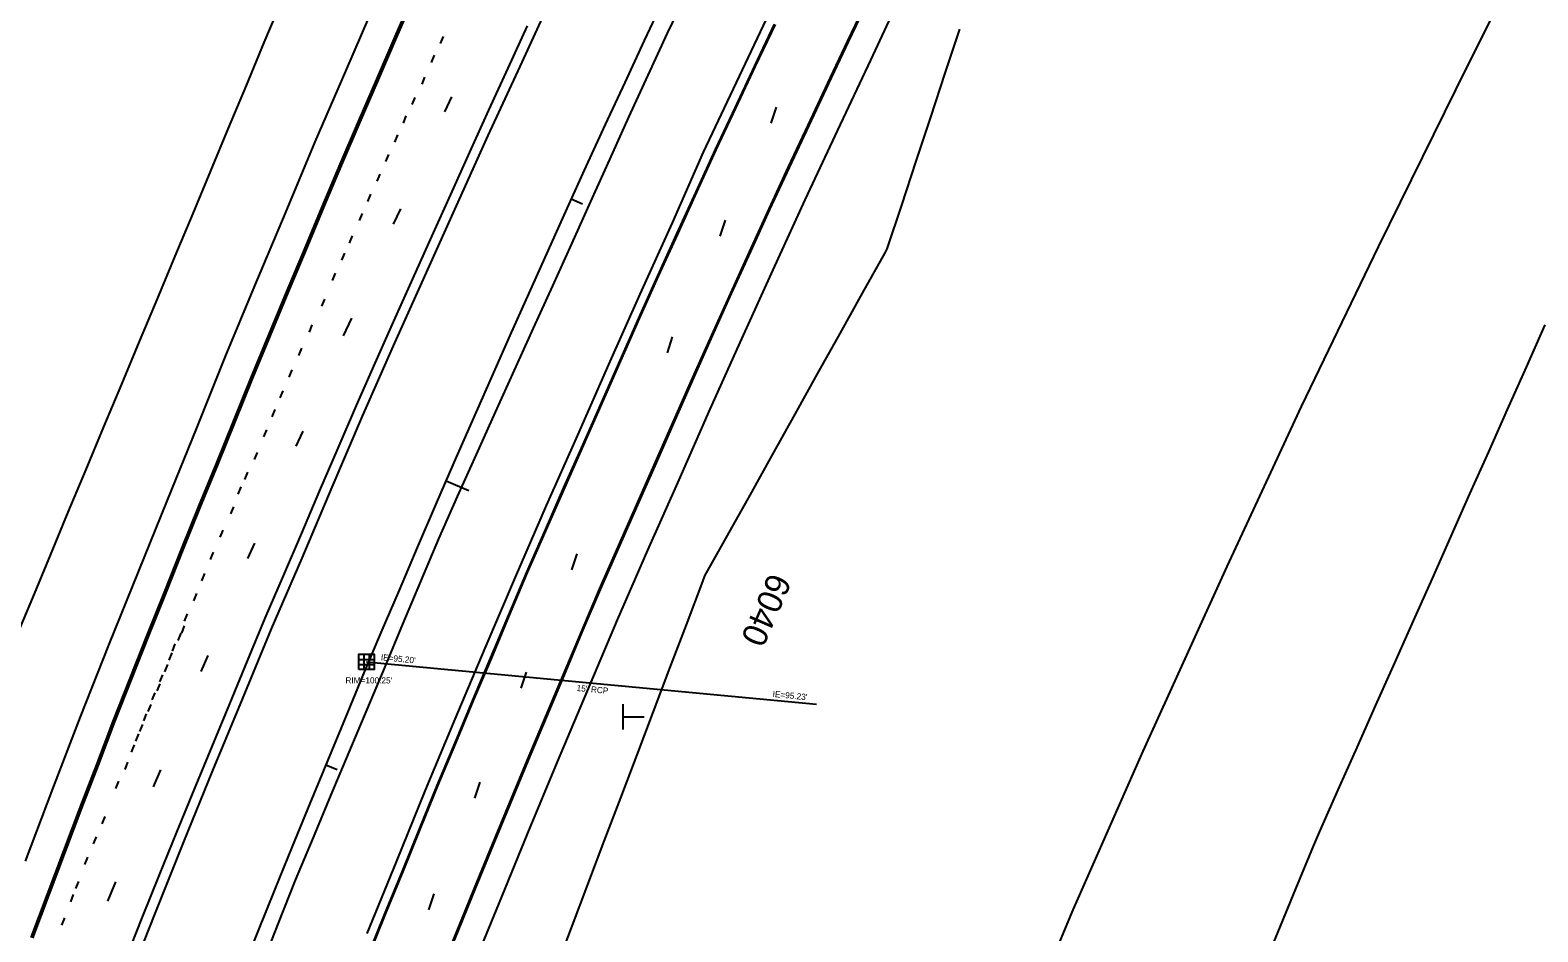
# Model space of a CAD drawing. Extents: x 2132221 to 2141942, y 535736 to 547298.
# Drawn here: x 2136377.6 to 2136866.6, y 537794.1 to 538086.4 of the extents above; entities that cross this region are included whole.
import ezdxf

# ---------------------------------------------------------------- set-up
doc = ezdxf.new("R2010")
doc.units = 0
for name, color, linetype in [('RD_EX_BldgApp', 7, 'Continuous'), ('RD_EX_Conc', 7, 'Continuous'), ('RD_EX_DR_Inlet', 7, 'Continuous'), ('RD_EX_DR_Inlet_txCode', 7, 'Continuous'), ('RD_EX_DR_Pipe', 7, 'Continuous'), ('RD_EX_DR_Pipe_txCode', 7, 'Continuous'), ('RD_EX_Fence_Other', 7, 'Continuous'), ('RD_EX_GuardRail', 7, 'Continuous'), ('RD_EX_Misc', 7, 'Continuous'), ('RD_EX_Road', 7, 'Continuous'), ('RD_EX_VEG', 7, 'Continuous'), ('RD_HC_Cl', 7, 'Continuous'), ('RD_HC_Data_Tic', 7, 'Continuous'), ('RD_HC_TX_Sta50', 7, 'Continuous'), ('TOPO_E_TLIML-Line', 7, 'Continuous')]:
    doc.layers.add(name, color=color, linetype=linetype)

msp = doc.modelspace()

# ---------------------------------------------------------------- linework, layer by layer
at = {"layer": 'RD_EX_BldgApp'}
for p, q in [((2136569.86, 537867.87), (2136569.86, 537863.75)), ((2136569.86, 537863.75), (2136569.86, 537859.64)), ((2136569.86, 537863.75), (2136576.72, 537863.75))]:
    msp.add_line(p, q, dxfattribs=at)
at = {"layer": 'RD_EX_Conc'}
for points in [[(2136377.94, 537792.23), (2136383.21, 537806.27), (2136388.51, 537820.3), (2136393.84, 537834.33), (2136399.18, 537848.34), (2136404.54, 537862.35), (2136409.99, 537876.34), (2136415.51, 537890.29), (2136421.11, 537904.2), (2136426.72, 537918.11), (2136432.35, 537932.02), (2136438, 537945.92), (2136443.63, 537959.82), (2136449.25, 537973.73), (2136454.98, 537987.59), (2136460.75, 538001.44), (2136466.53, 538015.28), (2136472.33, 538029.12), (2136478.15, 538042.95), (2136484.07, 538056.73), (2136490.02, 538070.5), (2136495.93, 538084.29), (2136501.94, 538098.03)], [(2136510.69, 537780.38), (2136516.36, 537794.27), (2136522.05, 537808.15), (2136527.73, 537822.03), (2136533.45, 537835.89), (2136539.22, 537849.74), (2136545.05, 537863.56), (2136550.89, 537877.38), (2136556.68, 537891.21), (2136562.58, 537905), (2136568.59, 537918.74), (2136574.67, 537932.45), (2136580.76, 537946.16), (2136586.79, 537959.9), (2136592.85, 537973.62), (2136598.94, 537987.32), (2136605.12, 538000.99), (2136611.32, 538014.65), (2136617.55, 538028.29), (2136623.86, 538041.9), (2136630.26, 538055.46), (2136636.63, 538069.04), (2136643.01, 538082.62), (2136649.46, 538096.16)], [(2136487.01, 537785.95), (2136492.62, 537799.86), (2136498.33, 537813.74), (2136503.97, 537827.63), (2136509.63, 537841.53), (2136515.4, 537855.37), (2136521.21, 537869.2), (2136527.05, 537883.02), (2136532.85, 537896.85), (2136538.69, 537910.67), (2136544.69, 537924.42), (2136550.74, 537938.15), (2136556.84, 537951.85), (2136562.88, 537965.58), (2136568.91, 537979.31), (2136575.01, 537993.02), (2136581.17, 538006.7), (2136587.39, 538020.35), (2136593.6, 538034), (2136599.84, 538047.65), (2136606.24, 538061.21), (2136612.65, 538074.77), (2136619.07, 538088.33)]]:
    msp.add_lwpolyline(points, dxfattribs=at)
at = {"layer": 'RD_EX_DR_Inlet'}
for p, q in [((2136484.16, 537882.41), (2136489.16, 537882.41)), ((2136485.86, 537884.11), (2136485.86, 537879.11)), ((2136487.56, 537884.11), (2136487.56, 537879.11)), ((2136484.16, 537880.71), (2136489.16, 537880.71))]:
    msp.add_line(p, q, dxfattribs=at)
msp.add_lwpolyline([(2136484.16, 537879.11), (2136484.16, 537884.11), (2136489.16, 537884.11), (2136489.16, 537879.11)], close=True, dxfattribs=at)
at = {"layer": 'RD_EX_DR_Pipe'}
msp.add_line((2136486.69, 537881.56), (2136632.62, 537867.86), dxfattribs=at)
at = {"layer": 'RD_EX_Fence_Other'}
msp.add_lwpolyline([(2136917.56, 538219.98), (2136890.82, 538168.74), (2136867.21, 538121.82), (2136843.5, 538074.27), (2136814.83, 538016.13), (2136789.9, 537964.36), (2136765.69, 537912.51), (2136738.54, 537852.61), (2136715.83, 537801.24), (2136694.15, 537749.42), (2136674.71, 537701.68), (2136655.13, 537652.11), (2136635.21, 537599.51), (2136616.78, 537549.09), (2136595.01, 537486.59), (2136577.24, 537436.55), (2136562.65, 537393.15), (2136547.82, 537347.2), (2136530.56, 537291.65)], dxfattribs=at)
at = {"layer": 'RD_EX_GuardRail'}
msp.add_lwpolyline([(2136452.64, 537782.88), (2136458.16, 537796.83), (2136463.67, 537810.78), (2136469.44, 537824.62), (2136475.25, 537838.45), (2136481.06, 537852.28), (2136486.88, 537866.11), (2136492.69, 537879.94), (2136498.5, 537893.76), (2136504.31, 537907.59), (2136510.12, 537921.42), (2136516.15, 537935.16), (2136522.33, 537948.82), (2136528.52, 537962.49), (2136534.7, 537976.15), (2136540.89, 537989.82), (2136547.07, 538003.48), (2136553.26, 538017.15), (2136559.44, 538030.82), (2136565.63, 538044.48), (2136571.81, 538058.15), (2136577.99, 538071.81), (2136584.35, 538085.4), (2136590.8, 538098.94)], dxfattribs=at)
at = {"layer": 'RD_EX_Misc'}
for p, q in [((2136510.7, 538082.02), (2136511.65, 538084.37)), ((2136507.77, 538075.91), (2136508.72, 538078.26)), ((2136504.7, 538068.83), (2136505.64, 538071.17)), ((2136501.52, 538062.23), (2136502.47, 538064.57)), ((2136512.07, 538059.95), (2136514.31, 538064.8)), ((2136498.64, 538056.22), (2136499.59, 538058.56)), ((2136617.98, 538056.23), (2136619.7, 538061.42)), ((2136495.91, 538050.08), (2136496.86, 538052.42)), ((2136492.98, 538043.76), (2136493.93, 538046.11)), ((2136490.13, 538037.4), (2136491.08, 538039.74)), ((2136487.13, 538030.83), (2136488.08, 538033.18)), ((2136495.41, 538023.43), (2136497.87, 538028.49)), ((2136484.4, 538024.63), (2136485.35, 538026.97)), ((2136601.37, 538019.61), (2136603.09, 538024.8)), ((2136481.22, 538017.34), (2136482.17, 538019.69)), ((2136478.68, 538011.77), (2136479.63, 538014.12)), ((2136475.65, 538005.27), (2136476.6, 538007.62)), ((2136472.18, 537996.88), (2136473.12, 537999.22)), ((2136468.16, 537988.5), (2136469.11, 537990.84)), ((2136479.26, 537987.26), (2136481.88, 537993.01)), ((2136584.26, 537981.74), (2136585.98, 537986.93)), ((2136464.74, 537980.88), (2136465.69, 537983.23)), ((2136461.59, 537973.9), (2136462.54, 537976.24)), ((2136458.69, 537967.14), (2136459.64, 537969.48)), ((2136456.09, 537961.03), (2136457.04, 537963.38)), ((2136453.37, 537954.5), (2136454.31, 537956.84)), ((2136463.87, 537951.48), (2136466.14, 537956.42)), ((2136450.35, 537947.17), (2136451.3, 537949.51)), ((2136447.19, 537940.75), (2136448.14, 537943.1)), ((2136445.05, 537935.96), (2136446, 537938.31)), ((2136442.66, 537929.55), (2136443.61, 537931.89)), ((2136439.19, 537921.96), (2136440.14, 537924.3)), ((2136436.12, 537914.82), (2136437.07, 537917.17)), ((2136448.23, 537915.14), (2136450.47, 537920.11)), ((2136553.27, 537911.4), (2136554.98, 537916.59)), ((2136433.28, 537907.88), (2136434.23, 537910.23)), ((2136430.67, 537901.37), (2136431.62, 537903.71)), ((2136427.66, 537894.78), (2136428.61, 537897.13)), ((2136425.61, 537888.53), (2136426.56, 537890.87)), ((2136426.73, 537890.92), (2136427.68, 537893.27)), ((2136423.71, 537885.06), (2136424.65, 537887.4)), ((2136422.68, 537882.17), (2136423.63, 537884.52)), ((2136433.02, 537878.48), (2136435.29, 537883.64)), ((2136419.65, 537875.09), (2136420.6, 537877.43)), ((2136421.31, 537878.36), (2136422.26, 537880.71)), ((2136536.85, 537873.02), (2136538.56, 537878.22)), ((2136417.2, 537869.24), (2136418.15, 537871.58)), ((2136418.77, 537872.16), (2136419.72, 537874.5)), ((2136415.88, 537865.47), (2136416.83, 537867.82)), ((2136414.41, 537862.44), (2136415.36, 537864.79)), ((2136411.87, 537855.89), (2136412.82, 537858.24)), ((2136413.19, 537858.97), (2136414.14, 537861.32)), ((2136410.46, 537852.32), (2136411.41, 537854.67)), ((2136408.36, 537846.75), (2136409.31, 537849.1)), ((2136405.38, 537840.55), (2136406.33, 537842.89)), ((2136417.59, 537841.07), (2136419.93, 537846.54)), ((2136521.87, 537837.39), (2136523.59, 537842.59)), ((2136400.93, 537829.11), (2136401.88, 537831.46)), ((2136398.15, 537822.56), (2136399.1, 537824.91)), ((2136395.32, 537815.91), (2136396.27, 537818.26)), ((2136392.44, 537808.09), (2136393.39, 537810.44)), ((2136402.74, 537803.99), (2136405.34, 537810.3)), ((2136390.73, 537803.79), (2136391.68, 537806.14)), ((2136506.89, 537801.15), (2136508.61, 537806.35)), ((2136387.9, 537796.27), (2136388.84, 537798.61))]:
    msp.add_line(p, q, dxfattribs=at)
for points in [[(2136378.48, 537792.02), (2136383.76, 537806.06), (2136389.06, 537820.1), (2136394.39, 537834.12), (2136399.73, 537848.13), (2136405.09, 537862.14), (2136410.53, 537876.12), (2136416.05, 537890.07), (2136421.65, 537903.99), (2136427.26, 537917.89), (2136432.89, 537931.8), (2136438.54, 537945.7), (2136444.17, 537959.6), (2136449.79, 537973.51), (2136455.52, 537987.37), (2136461.29, 538001.22), (2136467.07, 538015.06), (2136472.86, 538028.89), (2136478.68, 538042.72), (2136484.61, 538056.5), (2136490.56, 538070.27), (2136496.47, 538084.05), (2136502.47, 538097.8)], [(2136510.39, 537780.5), (2136516.06, 537794.39), (2136521.76, 537808.27), (2136527.43, 537822.15), (2136533.16, 537836.02), (2136538.93, 537849.86), (2136544.76, 537863.68), (2136550.59, 537877.5), (2136556.39, 537891.34), (2136562.29, 537905.13), (2136568.3, 537918.87), (2136574.38, 537932.58), (2136580.47, 537946.29), (2136586.5, 537960.03), (2136592.55, 537973.75), (2136598.65, 537987.45), (2136604.83, 538001.12), (2136611.03, 538014.78), (2136617.25, 538028.43), (2136623.57, 538042.03), (2136629.97, 538055.6), (2136636.34, 538069.18), (2136642.72, 538082.75), (2136649.17, 538096.3)], [(2136408.4, 537784.67), (2136413.93, 537798.61), (2136419.53, 537812.53), (2136425.15, 537826.43), (2136430.84, 537840.31), (2136436.57, 537854.18), (2136442.32, 537868.03), (2136448.08, 537881.88), (2136453.86, 537895.72), (2136459.81, 537909.49), (2136465.7, 537923.29), (2136471.53, 537937.11), (2136477.44, 537950.89), (2136483.39, 537964.66), (2136489.45, 537978.38), (2136495.54, 537992.09), (2136501.68, 538005.78), (2136507.83, 538019.46), (2136514, 538033.13), (2136520.16, 538046.81), (2136526.37, 538060.46), (2136532.61, 538074.1), (2136538.87, 538087.73)], [(2136487.24, 537785.86), (2136492.85, 537799.77), (2136498.56, 537813.64), (2136504.2, 537827.54), (2136509.86, 537841.43), (2136515.63, 537855.28), (2136521.44, 537869.11), (2136527.28, 537882.93), (2136533.08, 537896.76), (2136538.92, 537910.57), (2136544.91, 537924.32), (2136550.96, 537938.05), (2136557.07, 537951.75), (2136563.1, 537965.48), (2136569.14, 537979.21), (2136575.23, 537992.92), (2136581.4, 538006.6), (2136587.62, 538020.24), (2136593.83, 538033.9), (2136600.06, 538047.54), (2136606.47, 538061.11), (2136612.88, 538074.67), (2136619.3, 538088.22)]]:
    msp.add_lwpolyline(points, dxfattribs=at)
at = {"layer": 'RD_EX_Road'}
for points in [[(2136376.1, 537817), (2136384.98, 537840.38), (2136393.92, 537863.73), (2136403.07, 537887), (2136412.75, 537910.81), (2136422.11, 537934), (2136431.53, 537957.16), (2136440.87, 537980.36), (2136450.48, 538003.44), (2136460.37, 538027.1), (2136470.05, 538050.16), (2136479.98, 538073.11), (2136490.13, 538096.78)], [(2136408.91, 537776.83), (2136418.1, 537800.06), (2136427.45, 537823.25), (2136436.86, 537846.41), (2136446.43, 537869.51), (2136455.91, 537892.26), (2136465.82, 537915.21), (2136475.51, 537938.26), (2136485.39, 537961.22), (2136495.49, 537984.09), (2136505.59, 538006.63), (2136515.88, 538029.42), (2136526.19, 538052.19), (2136536.47, 538074.61), (2136546.91, 538097.32)], [(2136520.13, 537779.95), (2136529.61, 537803.04), (2136539.02, 537826.07), (2136548.62, 537849.15), (2136558.39, 537872.17), (2136568.06, 537895.22), (2136577.93, 537917.81), (2136588.1, 537940.65), (2136598.17, 537963.53), (2136608.41, 537986.34), (2136618.56, 538008.71), (2136628.92, 538031.39), (2136639.58, 538054), (2136650.24, 538076.62), (2136660.7, 538099.01)], [(2136486.88, 537793.58), (2136496.4, 537816.73), (2136505.81, 537840), (2136515.47, 537863.05), (2136525.22, 537886.07), (2136534.99, 537909.09), (2136545.09, 537932.25), (2136555.26, 537955.09), (2136565.3, 537977.98), (2136575.46, 538000.83), (2136585.95, 538023.88), (2136595.99, 538046.84), (2136606.67, 538069.44), (2136617.39, 538092.03)]]:
    msp.add_lwpolyline(points, dxfattribs=at)
at = {"layer": 'RD_EX_VEG'}
for points in [[(2136459.2, 538096.17), (2136453.42, 538082.33), (2136447.64, 538068.48), (2136441.86, 538054.64), (2136436.09, 538040.8), (2136430.31, 538026.96), (2136424.53, 538013.12), (2136418.75, 537999.28), (2136412.97, 537985.43), (2136407.19, 537971.59), (2136401.41, 537957.75), (2136395.63, 537943.91), (2136389.85, 537930.07), (2136384.07, 537916.22), (2136378.29, 537902.38), (2136372.51, 537888.54)], [(2136547.83, 537781.39), (2136553.15, 537795.41), (2136558.48, 537809.43), (2136563.81, 537823.45), (2136569.13, 537837.47), (2136574.46, 537851.5), (2136579.79, 537865.52), (2136585.11, 537879.54), (2136590.44, 537893.56), (2136595.77, 537907.59), (2136596.47, 537909.44), (2136603.78, 537922.54), (2136611.08, 537935.64), (2136618.39, 537948.74), (2136625.7, 537961.84), (2136633, 537974.94), (2136640.31, 537988.04), (2136647.61, 538001.14), (2136654.92, 538014.24), (2136655.59, 538015.44), (2136660.29, 538029.69), (2136664.99, 538043.93), (2136669.69, 538058.18), (2136674.39, 538072.42), (2136679.09, 538086.67)]]:
    msp.add_lwpolyline(points, dxfattribs=at)
at = {"layer": 'RD_HC_Cl'}
msp.add_arc((2141773.22, 535656.94), 5734.92, 149.115721, 168.327797, dxfattribs=at)
at = {"layer": 'RD_HC_Data_Tic'}
for p, q in [((2136553.09, 538031.7), (2136556.73, 538030.04)), ((2136512.48, 537940.32), (2136519.82, 537937.13)), ((2136473.46, 537848.24), (2136477.16, 537846.71))]:
    msp.add_line(p, q, dxfattribs=at)
at = {"layer": 'TOPO_E_TLIML-Line'}
msp.add_lwpolyline([(2136776.66, 537780.24), (2136782.39, 537794.1), (2136788.12, 537807.96), (2136793.86, 537821.83), (2136795.76, 537826.42), (2136801.87, 537840.12), (2136807.97, 537853.82), (2136814.08, 537867.53), (2136820.18, 537881.23), (2136826.29, 537894.93), (2136832.4, 537908.63), (2136838.5, 537922.33), (2136844.61, 537936.03), (2136850.72, 537949.73), (2136856.82, 537963.43), (2136862.93, 537977.13), (2136869.04, 537990.83)], dxfattribs=at)

# ---------------------------------------------------------------- texts
at = {"layer": 'RD_EX_DR_Inlet_txCode'}
for s, p in [("IE=95.20'", (2136491.27, 537882.13)), ("IE=95.23'", (2136618.34, 537870.21))]:
    msp.add_text(s, height=2, rotation=354.6391, dxfattribs=at).set_placement(p)
msp.add_text("RIM=100.25'", height=2, dxfattribs=at).set_placement((2136479.85, 537874.59))
at = {"layer": 'RD_EX_DR_Pipe_txCode'}
msp.add_text('15" RCP', height=2, rotation=354.6391, dxfattribs=at).set_placement((2136554.76, 537872.16))
at = {"layer": 'RD_HC_TX_Sta50'}
msp.add_text('6040', height=8, rotation=246.5372, dxfattribs=at).set_placement((2136617.44, 537910.89))

doc.saveas('drawing.dxf')
